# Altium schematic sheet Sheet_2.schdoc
size 290 x 219 mm
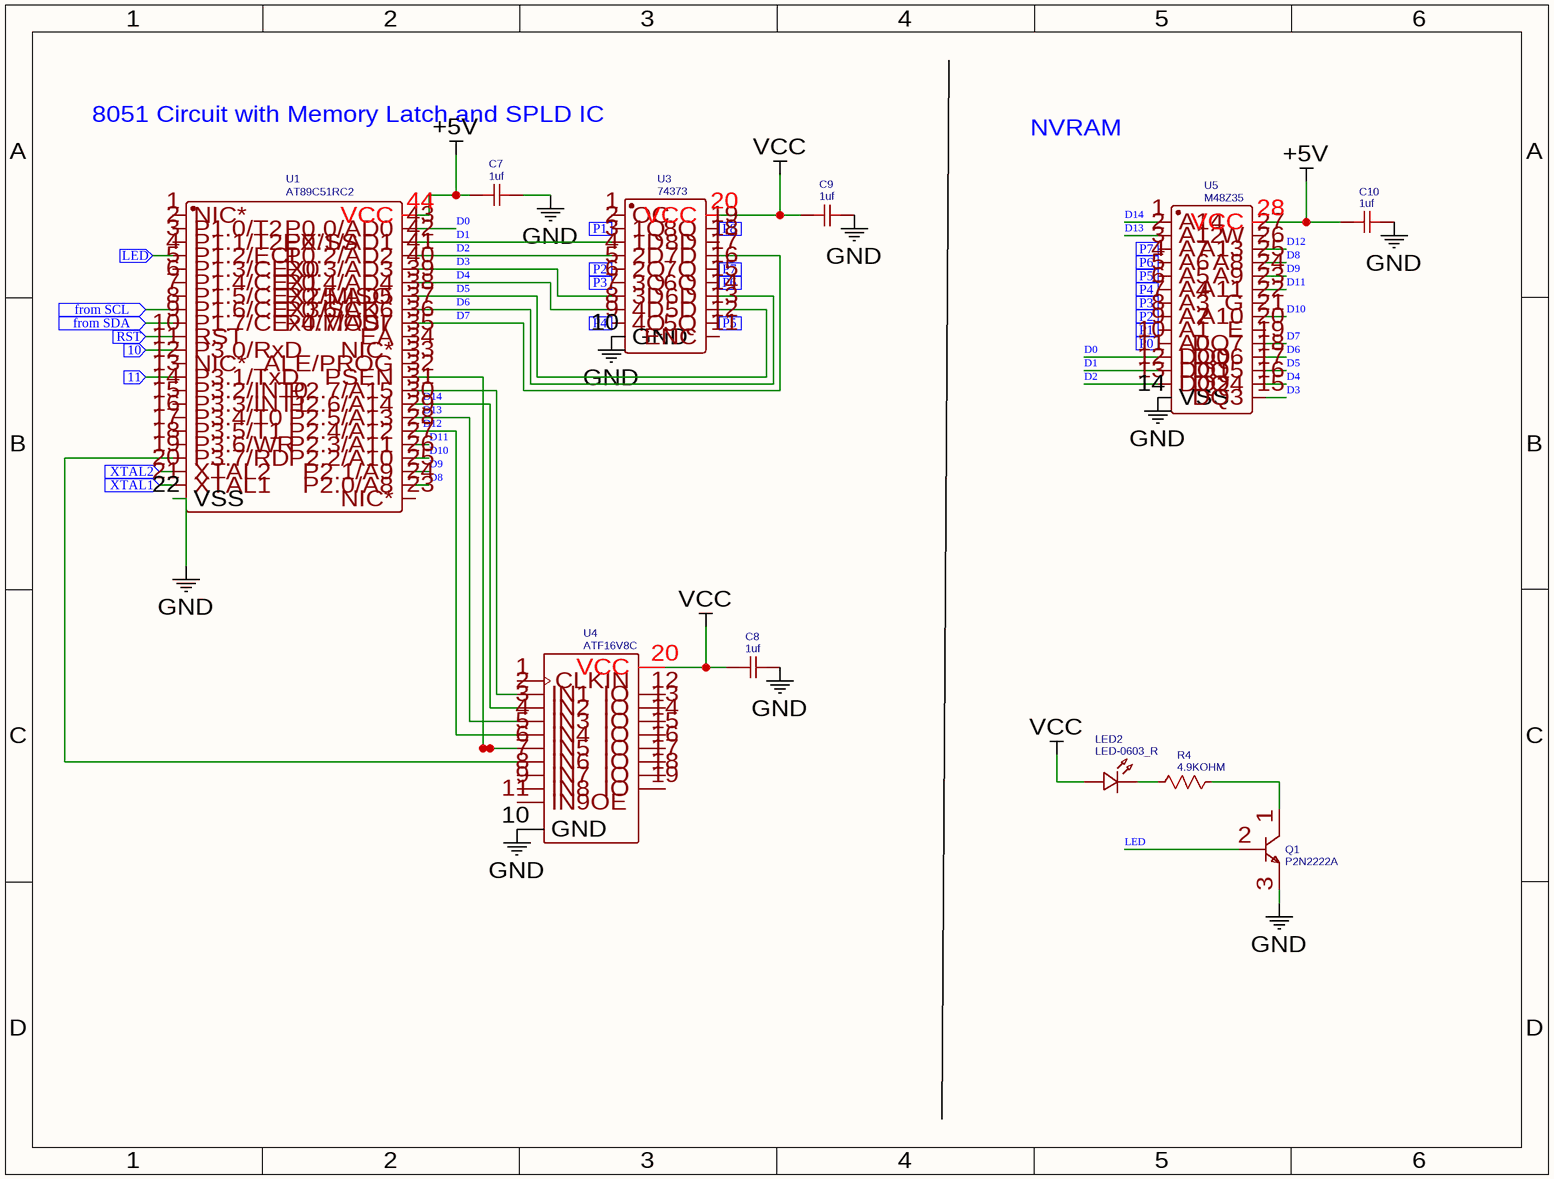
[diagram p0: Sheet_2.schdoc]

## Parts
C7  1uf  [C0603]
C8  1uf  [C0603]
C9  1uf  [C0603]
C10  1uf  [C0603]
LED2  LED-0603_R  [LED0603_RED]
Q1  P2N2222A  [ONSC-TO-92-3-29-11_AM_BL]
R4  4.9KOHM  [R0603]
U1  AT89C51RC2  [PLCC-44_L16.6-W16.6-P1.27-LS17.5-T]
U3  74373  [DIP20]
U4  ATF16V8C  [20X_N]
U5  M48Z35

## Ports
10 (in), 11 (in), from SCL (in), from SDA (in), LED (in), P0 (in), P1 (in), P2 (in), P3 (in), P4 (in), P5 (in), P6 (in), P7 (in), P8 (in), RST (in), XTAL1 (in), XTAL2 (in)

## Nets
+5V: C7.1 C10.1 U1.44(VCC) U5.28(VCC)
GND: C7.2 C8.2 C9.2 C10.2 Q1.3(E) U1.22(VSS) U3.10(GND) U4.10(GND) U5.14(VSS)
VCC: C8.1 C9.1 LED2.1 U3.20(VCC) U4.20(VCC)
10: U1.11(P3.0/RxD) ; port 10
11: U1.13(P3.1/TxD) ; port 11
D0: U1.43(P0.0/AD0) U5.11(DQ0)
D1: U1.42(P0.1/AD1) U3.3(1D) U5.12(DQ1)
D2: U1.41(P0.2/AD2) U3.4(2D) U5.13(DQ2)
D3: U1.40(P0.3/AD3) U3.7(3D) U5.15(DQ3)
D4: U1.39(P0.4/AD4) U3.8(4D) U5.16(DQ4)
D5: U1.38(P0.5/AD5) U3.13(5D) U5.17(DQ5)
D6: U1.37(P0.6/AD6) U3.14(6D) U5.18(DQ6)
D7: U1.36(P0.7/AD7) U3.17(7D) U5.19(DQ7)
D8: U1.24(P2.0/A8) U5.25(A8)
D9: U1.25(P2.1/A9) U5.24(A9)
D10: U1.26(P2.2/A10) U5.21(A10)
D11: U1.27(P2.3/A11) U5.23(A11)
D12: U1.28(P2.4/A12) U4.5(IN4) U5.26(A13)
D13: U1.29(P2.5/A13) U4.4(IN3) U5.2(A12)
D14: U1.30(P2.6/A14) U4.3(IN2) U5.1(A14)
from SCL: U1.8(P1.6/CEX3/SCK) ; port from SCL
from SDA: U1.9(P1.7/CEx4/MOSI) ; port from SDA
LED: U1.4(P1.2/ECI) ; port LED
LED: Q1.2(B)  [a separate net that carries the same name]
P0: U5.10(A0) ; port P0
P1: U3.2(1Q) U5.9(A1) ; port P1
P2: U3.5(2Q) U5.8(A2) ; port P2
P3: U3.6(3Q) U5.7(A3) ; port P3
P4: U3.9(4Q) U5.6(A4) ; port P4
P5: U3.12(5Q) U5.5(A5) ; port P5
P6: U3.15(6Q) U5.4(A6) ; port P6
P7: U3.16(7Q) U5.3(A7) ; port P7
P8: U3.19(8Q) ; port P8
RST: U1.10(RST) ; port RST
XTAL1: U1.21(XTAL1) ; port XTAL1
XTAL2: U1.20(XTAL2) ; port XTAL2
NetLED2_2: LED2.2 R4.1
NetQ1_1: Q1.1(C) R4.2
NetU1_19: U1.19(P3.7/RD) U4.7(IN6)
NetU1_31: U1.31(P2.7/A15) U4.2(IN1)
NetU1_32: U1.32(PSEN) U4.6(IN5)

Not connected (* = marked no-connect by the designer): U1 1(NIC*) 2(P1.0/T2) 3(P1.1/T2EX/SS) 5(P1.3/CEX0) 6(P1.4/CEX1) 7(P1.5/CEX2/MISO) 12(NIC*) 14(P3.2/INT0) 15(P3.3/INT1) 16(P3.4/T0) 17(P3.5/T1) 18(P3.6/WR) 23(NIC*) 33(ALE/PROG) 34(NIC*) 35(EA); U3 1(OC) 11(ENC) 18(8D); U4 1(CLKIN) 8(IN7) 9(IN8) 11(IN9OE) 12(IO) 13(IO) 14(IO) 15(IO) 16(IO) 17(IO) 18(IO) 19(IO); U5 20(E) 22(G) 27(W)

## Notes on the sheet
- 8051 Circuit with Memory Latch and SPLD IC
- NVRAM

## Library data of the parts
C7-C10 = 1uf: nameAlias: Value(F); Contributor: LCEDA_Lib
LED2 = LED-0603_R: BOM_Manufacturer: EVERLIGHT(台湾亿光); BOM_Manufacturer Part: 19-217/R6C-AL1M2VY/3T; Contributor: LCEDA_01
Q1 = P2N2222A: description: Amplifier Transistor, NPN Silicon, 3-Pin TO-92, Pb-Free, Tape and Reel
R4 = 4.9KOHM: nameAlias: Value(Ω); Contributor: LCEDA_Lib
U1 = AT89C51RC2: BOM_Manufacturer: null; BOM_Manufacturer Part: AT89C51RC2-SLSUL; Contributor: LCSC
U4 = ATF16V8C: description: ATF16V8CZ 5.0V Industry Standard SPLD, 20-lead TSSOP, Speed Grade 15, Industrial Grade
